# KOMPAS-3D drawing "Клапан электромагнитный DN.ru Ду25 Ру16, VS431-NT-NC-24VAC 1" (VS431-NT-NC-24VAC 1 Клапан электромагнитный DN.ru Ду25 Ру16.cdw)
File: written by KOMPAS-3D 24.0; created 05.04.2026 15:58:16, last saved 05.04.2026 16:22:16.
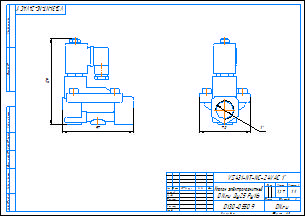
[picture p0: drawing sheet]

Document properties: c3d_UniqueCompID: ef56311e-7521-43dc-8291-0e6108b3d81d; Автор: artio; Класс точности: c; Знак неуказанной шероховатости: Шероховатость не задана; Рассекать на разрезах: Да; c3d_UniqueCompID: ef56311e-7521-43dc-8291-0e6108b3d81d; Автор: artio; Класс точности: c; Знак неуказанной шероховатости: Шероховатость не задана; Рассекать на разрезах: Да; Автор: artio; Форматы листов документа: A3; Полное имя файла: VS431-NT-NC-24VAC 1 Клапан электромагнитный DN.ru Ду25 Ру16.m3d; Масса: 1.267; Наименование: Клапан электромагнитный DN.ru Ду25 Ру16; Количество листов документа: 1; Примечание: D130-05509

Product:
- Body: Тело 1  | qty 1
    Масса: 1.729172
- Part/product: Клапан электромагнитный DN.ru Ду25 Ру16  | designation VS431-NT-NC-24VAC 1
    Масса: 1.267
    Раздел спецификации: Прочие изделия
    Примечание: D130-05509
    additional columns: ef56311e-7521-43dc-8291-0e6108b3d81d; artio; c; Шероховатость не задана; Да

Views: Вид 1, Спереди, Проекционный вид 2
Referenced files in C:\Users\artio\OneDrive\Рабочий стол\Клапан электромагнитный DN.ru\VS431\VS431-ET-NC\: VS431-ET-NC-24VAC 3-4 Клапан электромагнитный DN.ru Ду20 Ру16.m3d, VS431-ET-NC-24VAC 3-4 Клапан электромагнитный DN.ru Ду20 Ру16.cdw
Referenced files in C:\Users\artio\OneDrive\Рабочий стол\Клапан электромагнитный DN.ru\VS431\VS431-NT-NC\: VS431-NT-NC-24VAC 1 Клапан электромагнитный DN.ru Ду25 Ру16.m3d
Referenced files in C:\Users\artio\OneDrive\Рабочий стол\Клапан электромагнитный DN.ru\VS431\VS431-NT-NC\VS431-NT-NC-24VAC\Ду25\: VS431-NT-NC-24VAC 1 Клапан электромагнитный DN.ru Ду25 Ру16.m3d
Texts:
  VS431-NT-NC-24VAC 1
  Клапан электромагнитный
  DN.ru Ду25 Ру16
  VS431-NT-NC-24VAC 1"
  VS431-NT-NC-24VAC 1"-
  Клапан электромагнитный DN.ru Ду25 Ру16
  VS431-NT-NC-24VAC 1 Клапан электромагнитный DN.ru Ду25 Ру16
Dimensions and other numbers on the sheet: 0; 3; 2; 4; 70; 97; 119; 1:1; 1; 1,27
